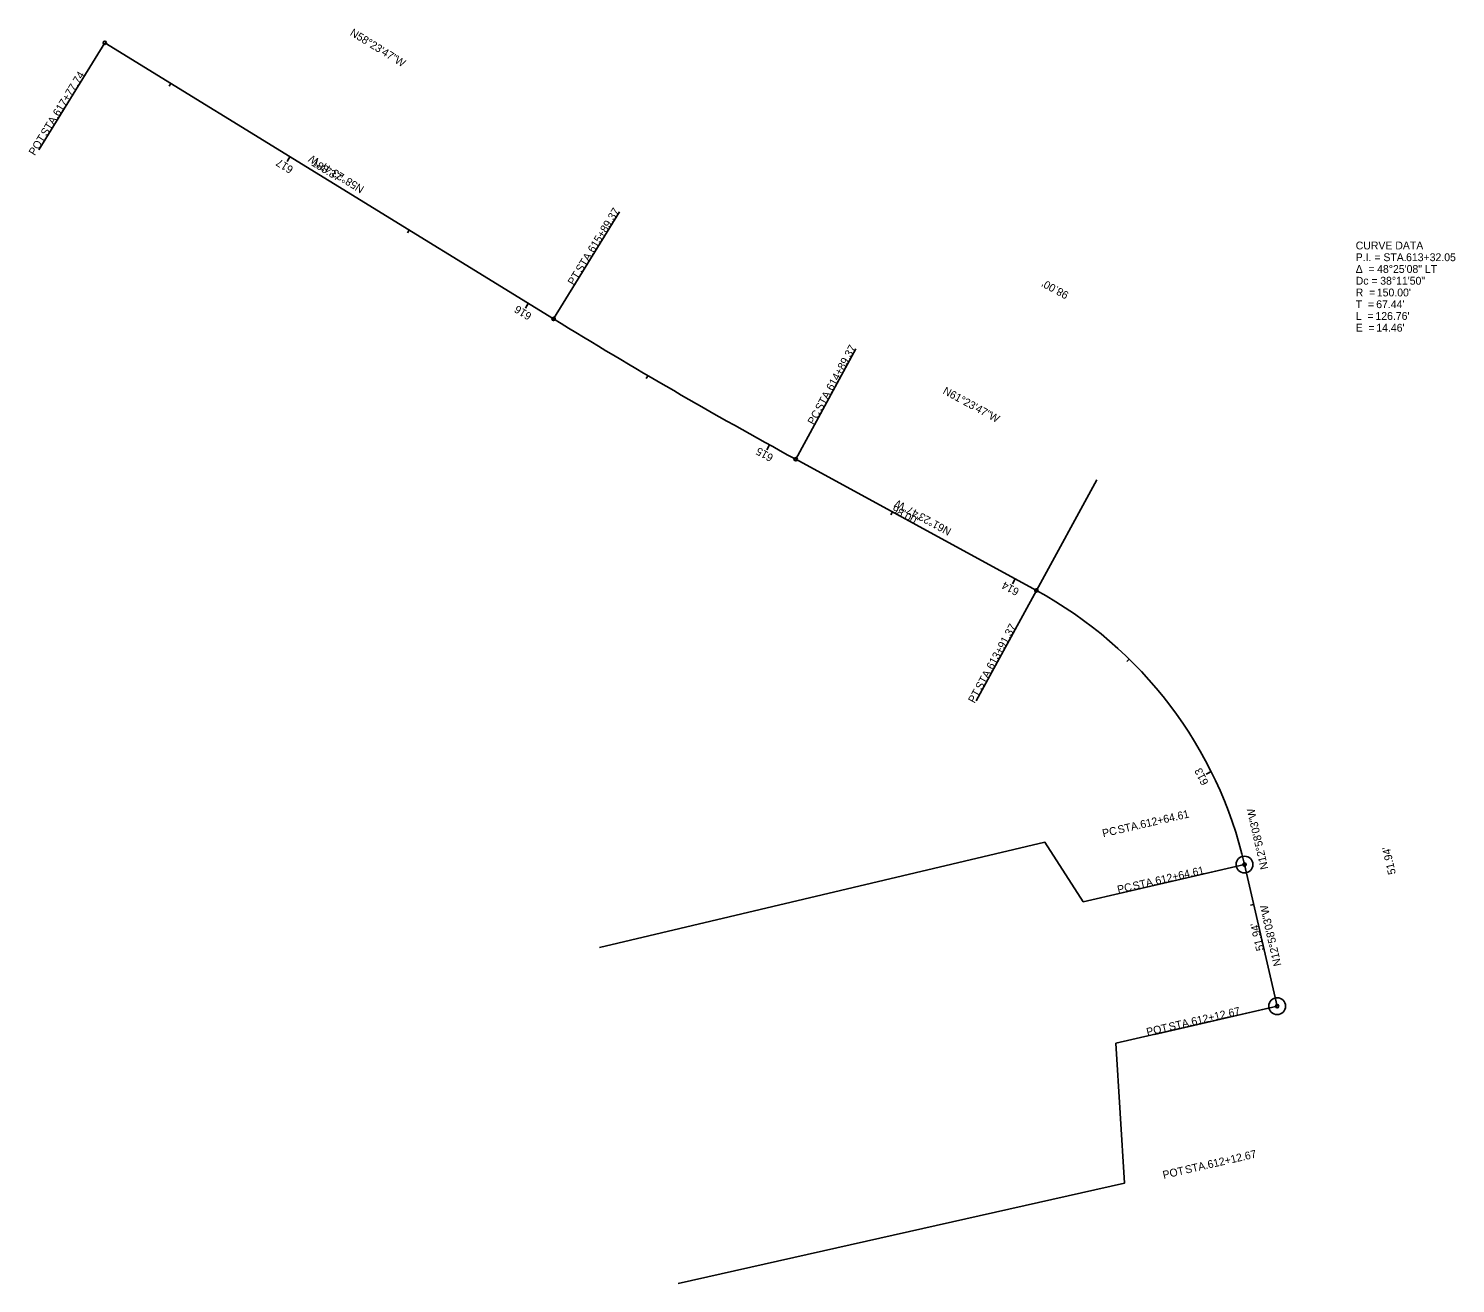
# Model space of a CAD drawing. Extents: x 1507135 to 1508660, y 327655 to 329219.
# Drawn here: x 1507135 to 1507645, y 328156 to 328605 of the extents above; entities that cross this region are included whole.
import ezdxf

# ---------------------------------------------------------------- set-up
doc = ezdxf.new("R2010")
doc.units = 0
for name, color, linetype in [('GE_X_Alignment', 7, 'Continuous'), ('GE_X_Alignment_100_Bearings', 7, 'Continuous'), ('GE_X_Alignment_100_Cardinal_Points', 7, 'Continuous'), ('GE_X_Alignment_100_Curve_Data', 7, 'Continuous'), ('GE_X_Alignment_100_Distances', 7, 'Continuous'), ('GE_X_Alignment_100_Stations', 7, 'Continuous'), ('GE_X_Alignment_500_Bearings', 7, 'Continuous'), ('GE_X_Alignment_500_Cardinal_Points', 7, 'Continuous'), ('GE_X_Alignment_500_Distances', 7, 'Continuous'), ('GE_X_Alignment_500_Stations', 7, 'Continuous')]:
    doc.layers.add(name, color=color, linetype=linetype)

msp = doc.modelspace()

# ---------------------------------------------------------------- linework, layer by layer
at = {"layer": 'GE_X_Alignment'}
for p, q in [((1507323.08, 328500.95), (1507162.65, 328599.66)), ((1507495.62, 328403.88), (1507409.58, 328450.8)), ((1507581.63, 328255.26), (1507569.98, 328305.88))]:
    msp.add_line(p, q, dxfattribs=at)
for centre, radius, start, end in [((1508323.99, 330127.69), 1910, 238.39647, 241.39625), ((1507423.81, 328272.19), 150, 12.9777, 61.3965)]:
    msp.add_arc(centre, radius, start, end, dxfattribs=at)
at = {"layer": 'GE_X_Alignment_100_Cardinal_Points'}
for p, q in [((1507162.65, 328599.66), (1507139.06, 328561.34)), ((1507323.08, 328500.95), (1507346.66, 328539.28)), ((1507409.58, 328450.8), (1507431.13, 328490.31)), ((1507495.62, 328403.88), (1507517.16, 328443.39))]:
    msp.add_line(p, q, dxfattribs=at)
for points in [[(1507569.98, 328305.88), (1507512.36, 328292.6), (1507498.67, 328313.85), (1507339.46, 328276.28)], [(1507581.63, 328255.26), (1507524.02, 328241.99), (1507527.13, 328192.03), (1507367.54, 328156.13)]]:
    msp.add_lwpolyline(points, dxfattribs=at)
for centre, radius in [((1507162.65, 328599.66), 0.6), ((1507323.08, 328500.95), 0.6), ((1507409.58, 328450.8), 0.6), ((1507495.62, 328403.88), 0.6), ((1507569.98, 328305.88), 3), ((1507581.63, 328255.26), 3)]:
    msp.add_circle(centre, radius, dxfattribs=at)
at = {"layer": 'GE_X_Alignment_100_Stations'}
for p, q in [((1507186.27, 328585.13), (1507185.64, 328584.11)), ((1507228.85, 328558.93), (1507227.81, 328557.22)), ((1507271.44, 328532.72), (1507270.81, 328531.7)), ((1507314.02, 328506.52), (1507312.98, 328504.82)), ((1507356.82, 328480.67), (1507356.21, 328479.63)), ((1507400.26, 328455.92), (1507399.29, 328454.17)), ((1507444.14, 328431.95), (1507443.57, 328430.9)), ((1507488.04, 328408.02), (1507487.08, 328406.26)), ((1507528.77, 328379.35), (1507527.93, 328378.5)), ((1507558.05, 328339.11), (1507556.26, 328338.22)), ((1507573.26, 328291.64), (1507572.09, 328291.37))]:
    msp.add_line(p, q, dxfattribs=at)
at = {"layer": 'GE_X_Alignment_500_Cardinal_Points'}
for p, q in [((1507162.65, 328599.66), (1507139.06, 328561.34)), ((1507323.08, 328500.95), (1507346.66, 328539.28)), ((1507409.58, 328450.8), (1507431.13, 328490.31)), ((1507495.62, 328403.88), (1507474.08, 328364.38)), ((1507569.98, 328305.88), (1507526.13, 328295.77)), ((1507581.63, 328255.26), (1507537.78, 328245.17))]:
    msp.add_line(p, q, dxfattribs=at)
for centre in [(1507162.65, 328599.66), (1507323.08, 328500.95), (1507409.58, 328450.8), (1507495.62, 328403.88), (1507569.98, 328305.88), (1507581.63, 328255.26)]:
    msp.add_circle(centre, 0.6, dxfattribs=at)
at = {"layer": 'GE_X_Alignment_500_Stations'}
for p, q in [((1507228.85, 328558.93), (1507228.23, 328557.9)), ((1507314.02, 328506.52), (1507313.39, 328505.5)), ((1507400.26, 328455.92), (1507399.29, 328454.17)), ((1507488.04, 328408.02), (1507487.47, 328406.96)), ((1507558.05, 328339.11), (1507556.98, 328338.58))]:
    msp.add_line(p, q, dxfattribs=at)

# ---------------------------------------------------------------- texts
at = {"layer": 'GE_X_Alignment_100_Bearings'}
for s, rotation, p in [('N58°23\'47"W', 328.3965, (1507250.08, 328602.54)), ('N61°23\'47"W', 331.3965, (1507461.92, 328474.39)), ('N12°58\'03"W', 102.9676, (1507578.49, 328304.47))]:
    msp.add_text(s, height=2.8, rotation=rotation, dxfattribs=at).set_placement(p)
at = {"layer": 'GE_X_Alignment_100_Cardinal_Points'}
for s, rotation, p in [('617+77.74', 58.3965, (1507146.29, 328573.14)), (' STA. ', 58.3965, (1507141.4, 328565.2)), ('POT', 58.3965, (1507137.66, 328559.13)), ('615+89.37', 58.3965, (1507337.45, 328524.38)), (' STA. ', 58.3965, (1507332.57, 328516.44)), ('PT', 58.3965, (1507330.29, 328512.73)), ('614+89.37', 61.3963, (1507422.77, 328475.06)), (' STA. ', 61.3963, (1507418.31, 328466.87)), ('PC', 61.3963, (1507416.1, 328462.83)), ('612+64.61', 12.9777, (1507533.06, 328318.77)), ('PC', 12.9777, (1507519.5, 328315.64)), (' STA. ', 12.9777, (1507523.98, 328316.67)), ('612+12.67', 12.9676, (1507557.12, 328197.21)), ('POT', 12.9676, (1507541.09, 328193.52)), (' STA. ', 12.9676, (1507548.04, 328195.12))]:
    msp.add_text(s, height=2.8, rotation=rotation, dxfattribs=at).set_placement(p)
at = {"layer": 'GE_X_Alignment_100_Curve_Data'}
for s, p in [('CURVE DATA', (1507609.72, 328525.8)), ('P.I. = STA. ', (1507609.72, 328521.6)), ('613+32.05', (1507627.71, 328521.6)), ('Δ  = ', (1507609.72, 328517.4)), ('48°25\'08" LT', (1507617.37, 328517.4)), ('Dc = ', (1507609.72, 328513.2)), ('R  = ', (1507609.72, 328509)), ("150.00'", (1507617.26, 328509)), ('38°11\'50"', (1507618.47, 328513.2)), ('T  = ', (1507609.72, 328504.8)), ("67.44'", (1507617.04, 328504.8)), ('L  = ', (1507609.72, 328500.6)), ("126.76'", (1507616.76, 328500.6)), ('E  = ', (1507609.72, 328496.4)), ("14.46'", (1507617.07, 328496.4))]:
    msp.add_text(s, height=2.8, dxfattribs=at).set_placement(p)
at = {"layer": 'GE_X_Alignment_100_Distances'}
for s, rotation, p in [("188.37'", 328.3965, (1507236.25, 328556)), ("98.00'", 331.3965, (1507443.6, 328431.96)), ("51.94'", 102.9676, (1507624.09, 328302.64))]:
    msp.add_text(s, height=2.8, rotation=rotation, dxfattribs=at).set_placement(p)
at = {"layer": 'GE_X_Alignment_100_Stations'}
for s, rotation, p in [('617', 148.3965, (1507230.31, 328555.1)), ('616', 148.3965, (1507315.49, 328502.69)), ('615', 151.0773, (1507401.86, 328452.18)), ('614', 151.3965, (1507489.72, 328404.25)), ('613', 116.4968, (1507557.24, 328335.13))]:
    msp.add_text(s, height=2.8, rotation=rotation, dxfattribs=at).set_placement(p)
at = {"layer": 'GE_X_Alignment_500_Bearings'}
for s, rotation, p in [('N58°23\'47"W', 148.3965, (1507255.62, 328548.09)), ('N61°23\'47"W', 151.3965, (1507465.46, 328425.8)), ('N12°58\'03"W', 102.9676, (1507583.18, 328269.92))]:
    msp.add_text(s, height=2.8, rotation=rotation, dxfattribs=at).set_placement(p)
at = {"layer": 'GE_X_Alignment_500_Cardinal_Points'}
for s, rotation, p in [('617+77.74', 58.3965, (1507146.29, 328573.14)), (' STA. ', 58.3965, (1507141.4, 328565.2)), ('POT', 58.3965, (1507137.66, 328559.13)), ('615+89.37', 58.3965, (1507337.45, 328524.38)), (' STA. ', 58.3965, (1507332.57, 328516.44)), ('PT', 58.3965, (1507330.29, 328512.73)), ('614+89.37', 61.3963, (1507422.77, 328475.06)), (' STA. ', 61.3963, (1507418.31, 328466.87)), ('PC', 61.3963, (1507416.1, 328462.83)), ('613+91.37', 61.3965, (1507480.02, 328375.36)), (' STA. ', 61.3965, (1507475.56, 328367.17)), ('PT', 61.3965, (1507473.48, 328363.35)), ('612+64.61', 12.9777, (1507538.43, 328298.64)), ('PC', 12.9777, (1507524.86, 328295.52)), (' STA. ', 12.9777, (1507529.34, 328296.55)), ('612+12.67', 12.9676, (1507551.29, 328248.31)), ('POT', 12.9676, (1507535.26, 328244.62)), (' STA. ', 12.9676, (1507542.21, 328246.22))]:
    msp.add_text(s, height=2.8, rotation=rotation, dxfattribs=at).set_placement(p)
at = {"layer": 'GE_X_Alignment_500_Distances'}
for s, rotation, p in [("98.00'", 151.3965, (1507507.41, 328510.32)), ("51.94'", 102.9676, (1507576.96, 328275.38))]:
    msp.add_text(s, height=2.8, rotation=rotation, dxfattribs=at).set_placement(p)
at = {"layer": 'GE_X_Alignment_500_Stations'}
msp.add_text('615', height=2.8, rotation=151.0773, dxfattribs=at).set_placement((1507401.86, 328452.18))

doc.saveas('drawing.dxf')
